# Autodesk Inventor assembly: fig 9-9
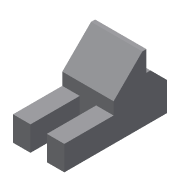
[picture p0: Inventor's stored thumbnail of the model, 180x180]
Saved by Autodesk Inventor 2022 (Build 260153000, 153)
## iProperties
Created: 2002-01
Part Number: fig 9-9
Document SubType Name: Assembly
Designer: ***
Control State: 0
Master: False
Checked Out: False
Shininess: 64.0
Length Units: 11269
Angle Units: 11279
Time Units: 11290
Mass Units: 11283
Length Display Precision: 3
Angle Display Precision: 2
Density: 0.0
Volumn: 0.0
Area: 0.0
PropertySet Name: Model Information
Author: ***
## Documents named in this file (3)
- D:\PROJECTS_2021\Resources\Part Files\c09_Inv_2022_prt\fig 9-9.iam
- D:\PROJECTS_2021\Resources\Part Files\c09_Inv_2022_prt\Part3.ipt
- D:\PROJECTS_2021\Resources\Part Files\c09_Inv_2022_prt\Part4.ipt
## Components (2 placed, 2 different names)
1. Part3:1 — Mate:1
2. Part4:1 — Mate:1
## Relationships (1: Mate 1)
- Mate:1: Part3:1 ↔ Part4:1
